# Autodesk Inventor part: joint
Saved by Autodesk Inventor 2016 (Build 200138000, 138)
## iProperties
Created: 2013-10
Part Number: joint
Material: solidworks materials|ABS
Document SubType Name: Modeling
Designer: Bruno
Density: 1.02 g/cm^3
Appearance: 255,255,255
Author: Bruno
Sending System: SolidWorks 2013
Last Author: christophe
Last Saved: 2014-02-15
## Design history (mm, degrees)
feature "Congé2"
node "Solide1"
